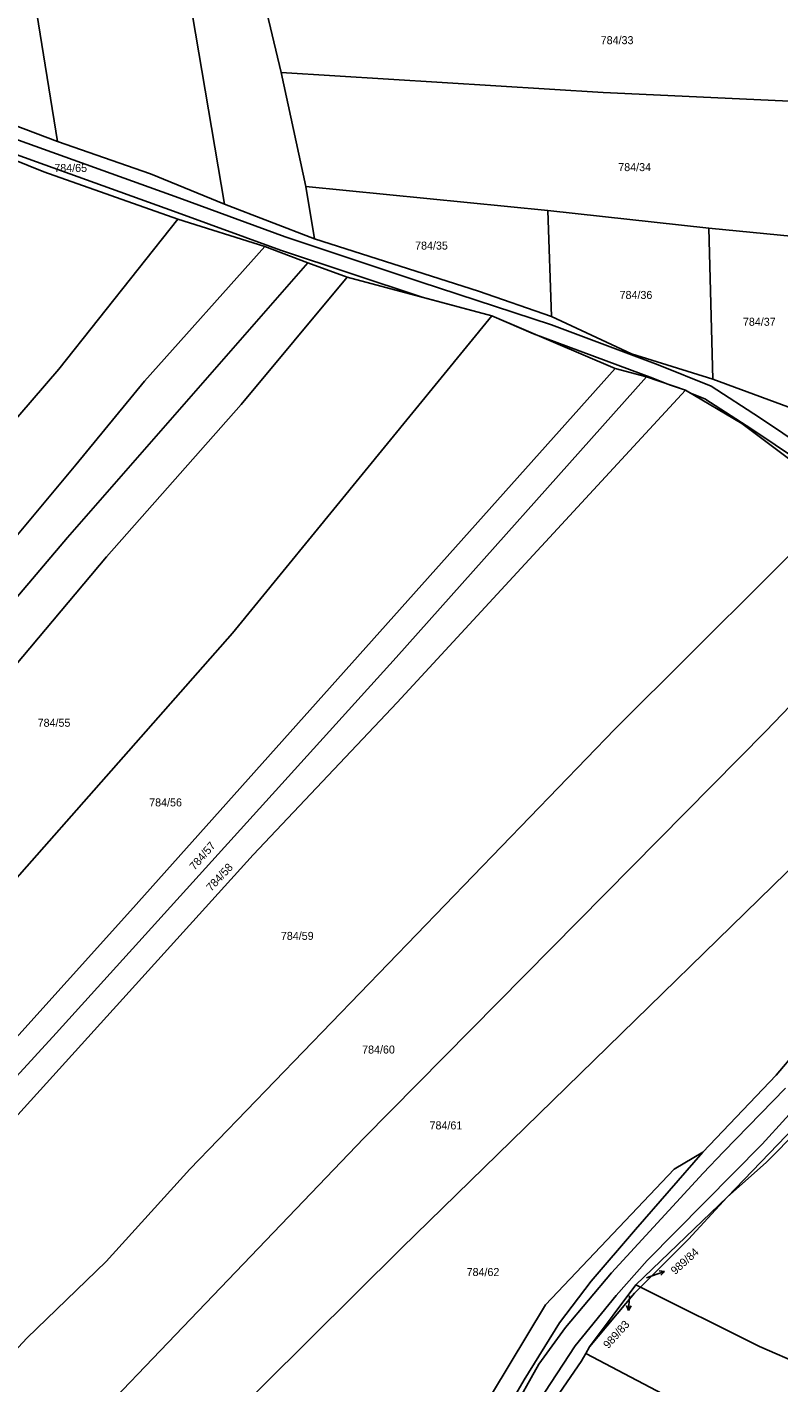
# Model space of a CAD drawing. Extents: x -757266 to -753360, y -1162585 to -1157740.
# Drawn here: x -756524.8 to -756365.2, y -1160406.8 to -1160118.8 of the extents above; entities that cross this region are included whole.
import ezdxf

# ---------------------------------------------------------------- set-up
doc = ezdxf.new("R2010")
doc.units = 0
for name, color, linetype in [('Hranice parcel', 7, 'Continuous'), ('Parcelní čísla', 7, 'Continuous'), ('Pop  PČ popisy', 7, 'Continuous'), ('Vnitřní kresba', 7, 'Continuous'), ('Věcná břemena k části', 7, 'Continuous')]:
    doc.layers.add(name, color=color, linetype=linetype)

msp = doc.modelspace()

# ---------------------------------------------------------------- linework, layer by layer
at = {"layer": 'Hranice parcel'}
for p, q in [((-756470.86, -1160128.46), (-756476.81, -1160103.31)), ((-756465.59, -1160152.67), (-756470.86, -1160128.46)), ((-756527.71, -1160139.59), (-756518.35, -1160143.12)), ((-756465.59, -1160152.67), (-756414.25, -1160157.78)), ((-756463.81, -1160163.79), (-756465.59, -1160152.67)), ((-756482.86, -1160156.39), (-756463.81, -1160163.79)), ((-756414.25, -1160157.78), (-756380.07, -1160161.51)), ((-756413.49, -1160180.31), (-756414.25, -1160157.78)), ((-756474.32, -1160165.39), (-756492.8, -1160159.61)), ((-756380.07, -1160161.51), (-756359.01, -1160163.55)), ((-756379.22, -1160193.56), (-756380.07, -1160161.51)), ((-756465.2, -1160168.86), (-756474.32, -1160165.39)), ((-756456.82, -1160171.92), (-756465.2, -1160168.86)), ((-756426.16, -1160180.16), (-756456.82, -1160171.92)), ((-756399.92, -1160191.29), (-756426.16, -1160180.16)), ((-756393.31, -1160193.12), (-756399.92, -1160191.29)), ((-756385.01, -1160195.93), (-756393.31, -1160193.12)), ((-756379.22, -1160193.56), (-756356.59, -1160201.94)), ((-756395.58, -1160385.93), (-756376.19, -1160367.36)), ((-756405.37, -1160399.15), (-756395.58, -1160385.93)), ((-756394.58, -1160386.43), (-756395.58, -1160385.93)), ((-756405.37, -1160399.15), (-756406.17, -1160400.53))]:
    msp.add_line(p, q, dxfattribs=at)
for points in [[(-756518.35, -1160143.12), (-756533.24, -1160051.42), (-756537.36, -1160018.14), (-756540.69, -1159998.89), (-756547.37, -1159947.03)], [(-756482.86, -1160156.39), (-756493.19, -1160095.81), (-756506.61, -1160027.62), (-756520.11, -1159948.54)], [(-756470.86, -1160128.46), (-756402.49, -1160132.67), (-756337.01, -1160135.74)], [(-756518.35, -1160143.12), (-756498.58, -1160149.96), (-756482.86, -1160156.39)], [(-756492.8, -1160159.61), (-756521.25, -1160149.55), (-756531.33, -1160145.51)], [(-756612.07, -1160303.14), (-756597.92, -1160287.45), (-756575.81, -1160259.66), (-756546.05, -1160223.88), (-756518.07, -1160191.45), (-756492.8, -1160159.61)], [(-756606.29, -1160320), (-756551.09, -1160255.9), (-756537.89, -1160239.82), (-756514.48, -1160211.78), (-756499.89, -1160194.01), (-756474.32, -1160165.39)], [(-756463.81, -1160163.79), (-756428.95, -1160174.88), (-756413.49, -1160180.31)], [(-756603.21, -1160328.99), (-756570.38, -1160291.11), (-756516.2, -1160227.25), (-756465.2, -1160168.86)], [(-756600, -1160338.36), (-756550.17, -1160281.57), (-756507.98, -1160231.33), (-756479.36, -1160198.95), (-756456.82, -1160171.92)], [(-756589.77, -1160368.2), (-756554.35, -1160330.52), (-756481.21, -1160247.51), (-756426.16, -1160180.16)], [(-756413.49, -1160180.31), (-756396.46, -1160188.2), (-756379.22, -1160193.56)], [(-756581.47, -1160392.42), (-756556.05, -1160365.57), (-756502.87, -1160306.55), (-756399.92, -1160191.29)], [(-756579.32, -1160398.69), (-756518.62, -1160332.51), (-756446.42, -1160252.68), (-756393.31, -1160193.12)], [(-756577.47, -1160404.07), (-756535.61, -1160359.58), (-756476.82, -1160294.64), (-756446.21, -1160262.26), (-756385.01, -1160195.93)], [(-756351.25, -1160219.36), (-756373.04, -1160203.04), (-756385.01, -1160195.93)], [(-756564.34, -1160439.83), (-756524.89, -1160397.27), (-756508.04, -1160380.97), (-756490.27, -1160361.41), (-756400.01, -1160267.91), (-756351.25, -1160219.36)], [(-756550.98, -1160456.74), (-756453.29, -1160354.79), (-756367.97, -1160268.36), (-756334.99, -1160233.99)], [(-756537.01, -1160470.55), (-756503.84, -1160436.32), (-756445.28, -1160378.18), (-756325.59, -1160261.34)], [(-756381.35, -1160357.77), (-756365.72, -1160341.45), (-756357.15, -1160331.21)], [(-756376.19, -1160367.36), (-756361.85, -1160352.47), (-756361.04, -1160353.06)], [(-756361.04, -1160353.06), (-756367.83, -1160359.91), (-756376.19, -1160367.36)], [(-756517.76, -1160483.82), (-756468.47, -1160450.07), (-756438.19, -1160426.27), (-756429.93, -1160415.48), (-756414.75, -1160390.2), (-756387.38, -1160361.42), (-756381.35, -1160357.77)], [(-756429.25, -1160423.49), (-756428.64, -1160422.22), (-756419.28, -1160406.1), (-756411.75, -1160394.04), (-756405.07, -1160385.14), (-756395.64, -1160374.22), (-756381.35, -1160357.77)], [(-756376.19, -1160367.36), (-756384.4, -1160376.27), (-756394.58, -1160386.43)], [(-756394.58, -1160386.43), (-756395.86, -1160387.7), (-756405.37, -1160399.15)], [(-756195.68, -1160474.33), (-756238.74, -1160452.9), (-756323.65, -1160418.88), (-756369.26, -1160399.04), (-756394.58, -1160386.43)], [(-756406.17, -1160400.53), (-756407.18, -1160402.27), (-756412.47, -1160409.97), (-756415.59, -1160416.48)], [(-756206.37, -1160496.92), (-756237.49, -1160481.05), (-756306.32, -1160451.34), (-756362.59, -1160423.45), (-756406.17, -1160400.53)]]:
    msp.add_lwpolyline(points, dxfattribs=at)
at = {"layer": 'Pop  PČ popisy'}
for p, q in [((-756393.29, -1160384.45), (-756392.31, -1160384.11)), ((-756392.31, -1160384.11), (-756389.473, -1160383.133)), ((-756389.473, -1160383.133), (-756390.582, -1160382.986)), ((-756389.473, -1160383.133), (-756390.256, -1160383.932)), ((-756396.87, -1160388.31), (-756396.88, -1160388.4)), ((-756397.089, -1160391.394), (-756397.519, -1160390.36)), ((-756396.88, -1160388.4), (-756397.089, -1160391.394)), ((-756397.089, -1160391.394), (-756396.52, -1160390.43))]:
    msp.add_line(p, q, dxfattribs=at)
at = {"layer": 'Vnitřní kresba'}
for p, q in [((-756368.75, -1160356.08), (-756351.24, -1160336.75)), ((-756363.77, -1160344.18), (-756376.94, -1160357.72)), ((-756393.17, -1160380.77), (-756368.75, -1160356.08)), ((-756376.94, -1160357.72), (-756381.22, -1160362.23)), ((-756381.22, -1160362.23), (-756400.72, -1160383.44)), ((-756399.76, -1160388.2), (-756393.17, -1160380.77)), ((-756400.72, -1160383.44), (-756410.52, -1160395.04)), ((-756408.43, -1160398.91), (-756399.76, -1160388.2)), ((-756410.52, -1160395.04), (-756416.14, -1160402.77)), ((-756414.86, -1160408.72), (-756408.43, -1160398.91)), ((-756416.14, -1160402.77), (-756422.41, -1160413.93))]:
    msp.add_line(p, q, dxfattribs=at)
at = {"layer": 'Věcná břemena k části'}
for points in [[(-756349.44, -1160215.07), (-756369.31, -1160201.7), (-756379.54, -1160195.11), (-756390.84, -1160190.57), (-756413.44, -1160182.02), (-756441.33, -1160172.9), (-756470, -1160163.36), (-756492.61, -1160155.11), (-756594.02, -1160118.62)], [(-756595.04, -1160121.46), (-756493.75, -1160157.9), (-756470.97, -1160166.19), (-756440.9, -1160176.2), (-756426.16, -1160180.16), (-756417.26, -1160183.94), (-756391.91, -1160193.37), (-756388.38, -1160194.79), (-756385.01, -1160195.93), (-756383.91, -1160196.58), (-756380.91, -1160197.79), (-756370.95, -1160204.21), (-756351.33, -1160217.41)]]:
    msp.add_lwpolyline(points, dxfattribs=at)

# ---------------------------------------------------------------- texts
at = {"layer": 'Parcelní čísla'}
for s, p in [('784/33', (-756403.01, -1160122.44)), ('784/65', (-756519.03, -1160149.58)), ('784/34', (-756399.28, -1160149.4)), ('784/35', (-756442.42, -1160166.07)), ('784/36', (-756399, -1160176.55)), ('784/37', (-756372.81, -1160182.25)), ('784/55', (-756522.57, -1160267.42)), ('784/56', (-756498.88, -1160284.34)), ('784/59', (-756470.92, -1160312.69)), ('784/60', (-756453.67, -1160336.83)), ('784/61', (-756439.35, -1160352.94)), ('784/62', (-756431.48, -1160384.09))]:
    msp.add_text(s, height=1.7, dxfattribs=at).set_placement(p)
for s, rotation, p in [('784/57', 49, (-756489.228, -1160298.017)), ('784/58', 47, (-756485.698, -1160302.489)), ('989/84', 42, (-756387.201, -1160383.891)), ('989/83', 48, (-756401.405, -1160399.633))]:
    msp.add_text(s, height=1.7, rotation=rotation, dxfattribs=at).set_placement(p)

doc.saveas('drawing.dxf')
